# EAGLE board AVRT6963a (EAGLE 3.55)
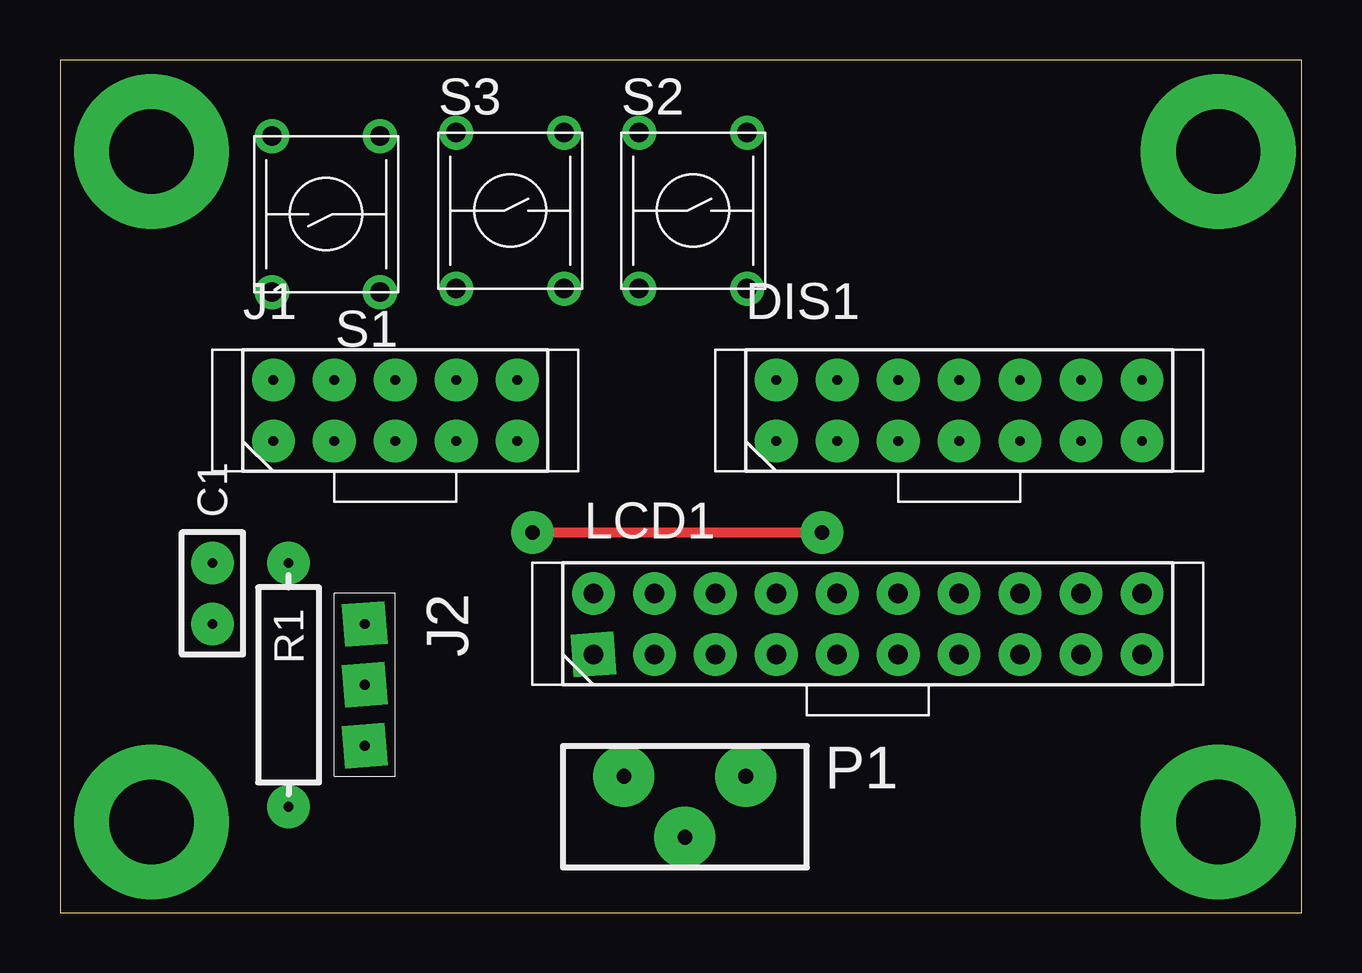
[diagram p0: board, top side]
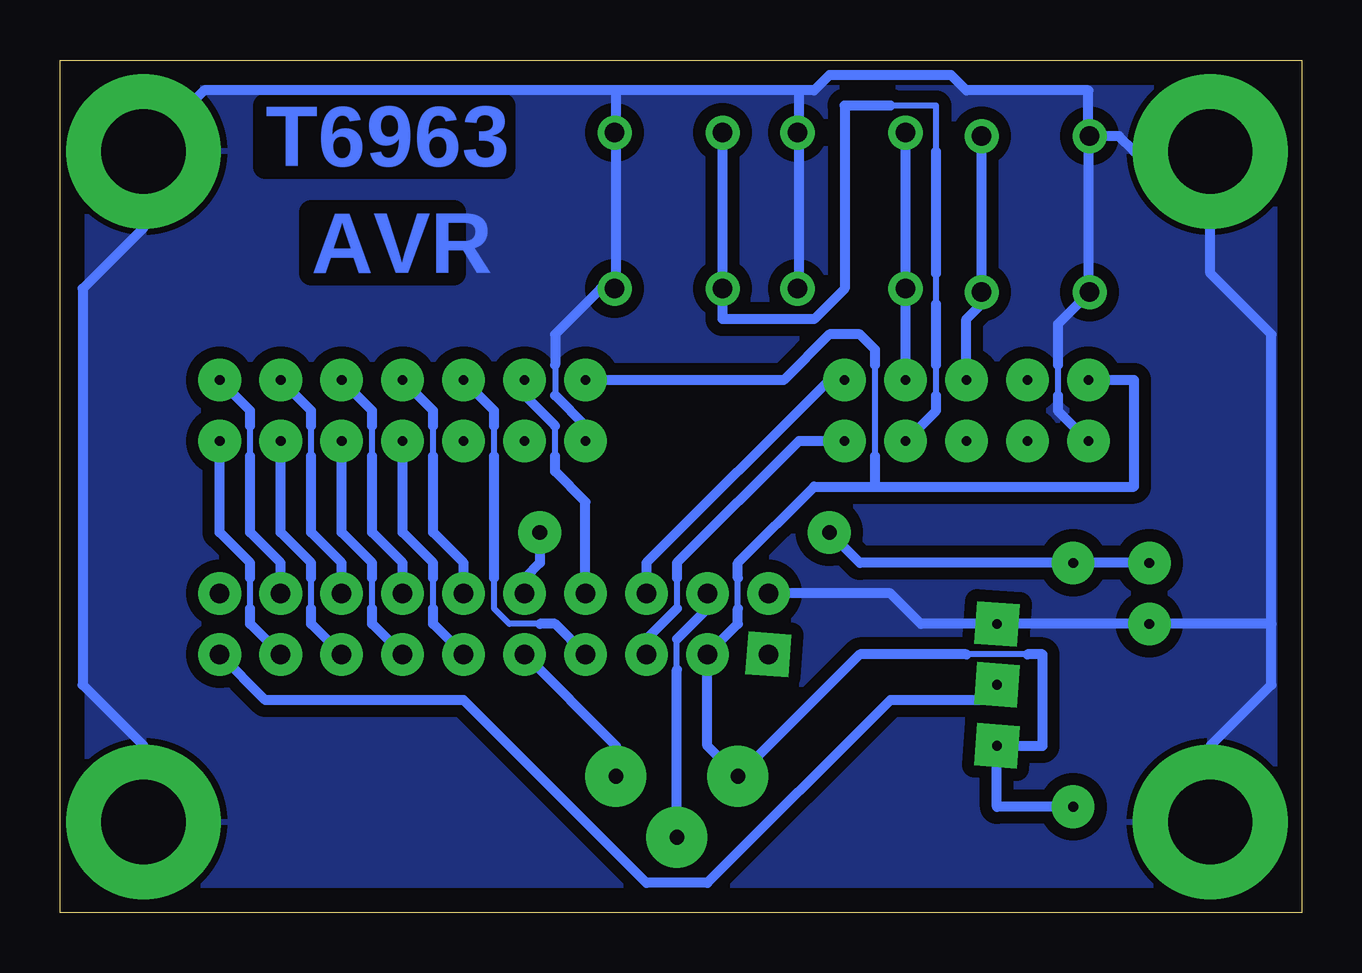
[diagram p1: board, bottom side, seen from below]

Size 51.74 x 35.54 mm. Coordinates in mm from the lower left corner, seen from the top.
Outline: 0,35.54 0,0 51.74,0 51.74,35.54 0,35.54
Copper layers used: Top, Bottom

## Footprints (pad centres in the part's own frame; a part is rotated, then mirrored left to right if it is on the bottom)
RM2,5 = drill 0.406 pad 1.778 round:  -1.27,0;  1.27,0
7 = drill 0.406 pad 1.778 round:  0,0;  2.54,0;  5.08,0;  7.62,0;  10.16,0;  10.16,2.54;  7.62,2.54;  5.08,2.54;  2.54,2.54;  0,2.54;  12.7,0;  12.7,2.54;  15.24,0;  15.24,2.54
5 = drill 0.406 pad 1.778 round:  0,0;  2.54,0;  5.08,0;  7.62,0;  10.16,0;  10.16,2.54;  7.62,2.54;  5.08,2.54;  2.54,2.54;  0,2.54
MPER_3 = drill 0.406 pad 1.778 square:  -2.54,0;  0,0;  2.54,0
10 = drill 0.813 pad 1.778 square:  0,0 | drill 0.813 pad 1.778 round:  2.54,0;  5.08,0;  7.62,0;  10.16,0;  12.7,0;  15.24,0;  15.24,2.54;  12.7,2.54;  10.16,2.54;  7.62,2.54;  5.08,2.54;  2.54,2.54;  0,2.54;  17.78,0;  17.78,2.54;  20.32,0;  20.32,2.54;  22.86,0;  22.86,2.54
IM_STE = drill 0.61 pad 2.54 round:  -2.54,-1.27;  2.54,-1.27;  0,1.27
S04 = drill 0.406 pad 1.778 round:  -5.08,0;  5.08,0
US = drill 0.813 pad 1.422 round:  0,0;  4.5,0;  4.5,6.5;  0,6.5
HRUNG = drill 3.505 pad 6.452 round:  0,0

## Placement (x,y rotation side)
C1  C100NK  [RM2,5]  6.35,13.32 90 top
DIS1  LCD  [7]  29.84,19.66 0 top
J1  8BITPORT  [5]  8.89,19.66 0 top
J2  JUMPER_3  [MPER_3]  12.7,9.51 270 top
LCD1  WG24064A  [10]  22.23,10.78 0 top
P1  47k  [IM_STE]  26.04,4.43 180 top
R1  10k  [S04]  9.53,9.51 270 top
S1  [US]  13.34,32.36 180 top
S2  [US]  24.13,26.02 0 top
S3  [US]  16.51,26.02 0 top
U$4  BOHRUNG  [HRUNG]  48.26,3.79 270 top
U$9  BOHRUNG  [HRUNG]  3.81,3.79 270 top
U$16  BOHRUNG  [HRUNG]  3.81,31.73 0 top
U$17  BOHRUNG  [HRUNG]  48.26,31.73 0 top

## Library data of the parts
C1 DIS1 J1 J2 LCD1 P1 R1 = holg_plt
S1-S3 = taster1
U$4 U$9 U$16 U$17 = holgnorm

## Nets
+5V: DIS1. J1. J2. LCD1. P1. R1.
/CE: DIS1. LCD1.
/RD: J1. LCD1.
/WR: J1. LCD1.
A0: DIS1. LCD1.
D0: DIS1. LCD1.
D1: DIS1. LCD1.
D2: DIS1. LCD1.
D3: DIS1. LCD1.
D4: DIS1. LCD1.
D5: DIS1. LCD1.
D6: DIS1. LCD1.
D7: DIS1. LCD1.
GND: C1. DIS1. J1. J2. LCD1. S1. S2. S3. U$4. U$9. U$16. U$17.
N$1: J1. S3.
N$2: C1. LCD1. R1.
N$3: J2. LCD1.
N$4: LCD1. P1.
N$5: LCD1. P1.
N$6: J1. S2.
N$7: J1. S1.

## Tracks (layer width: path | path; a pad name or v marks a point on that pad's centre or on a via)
+5V
  Bottom 0.254: 17.78,19.03 17.78,22.84 | 23.5,12.68 23.5,13.95 | 11.43,10.78 13.97,10.78
  Bottom 0.406: J1. 6.99,22.21 6.99,17.76 17.78,17.76 | R1. 12.7,4.43 J2. 10.79,6.97 10.79,10.78 11.43,10.78 | 29.84,22.21 21.59,22.21 19.68,24.11 18.41,24.11 17.78,23.48 17.78,22.84 | 17.78,17.76 17.78,19.03 | 23.5,12.68 23.5,12.04 24.77,10.78 24.77,6.97 23.5,5.7 18.41,10.78 13.97,10.78 | 23.5,13.95 23.5,14.59 20.32,17.76 17.78,17.76
/CE
  Bottom 0.254: 33.66,19.03 33.66,20.3 | 31.75,12.04 33.02,12.04 33.66,12.68 33.66,13.95
  Bottom 0.406: 29.84,10.78 31.11,12.04 31.75,12.04 | 34.92,22.21 33.66,20.93 33.66,20.3 | 33.66,13.95 33.66,19.03
/RD
  Bottom 0.406: 19.05,22.21 19.68,22.21 27.3,14.59 27.3,13.32
/WR
  Bottom 0.254: 26.04,13.95 26.04,12.68
  Bottom 0.406: 19.05,19.66 20.95,19.66 26.04,14.59 26.04,13.95 | 27.3,10.78 27.3,11.41 26.04,12.68
A0
  Bottom 0.254: 31.11,19.03 31.11,20.3
  Bottom 0.406: 32.38,22.21 32.38,21.57 31.11,20.3 | 29.84,13.32 29.84,17.12 31.11,18.39 31.11,19.03
D0
  Bottom 0.254: 36.2,12.68 36.2,13.95
  Bottom 0.406: 34.92,10.78 36.2,12.04 36.2,12.68 | 37.47,19.66 37.47,15.86 36.2,14.59 36.2,13.95
D1
  Bottom 0.254: 36.2,19.03 36.2,20.3
  Bottom 0.406: 37.47,22.21 36.2,20.93 36.2,20.3 | 34.92,13.32 34.92,14.59 36.2,15.86 36.2,19.03
D2
  Bottom 0.254: 38.73,12.68 38.73,13.95
  Bottom 0.406: 37.47,10.78 38.73,12.04 38.73,12.68 | 40.01,19.66 40.01,15.86 38.73,14.59 38.73,13.95
D3
  Bottom 0.254: 38.73,19.03 38.73,20.3
  Bottom 0.406: 40.01,22.21 38.73,20.93 38.73,20.3 | 37.47,13.32 37.47,14.59 38.73,15.86 38.73,19.03
D4
  Bottom 0.254: 41.27,12.68 41.27,13.95
  Bottom 0.406: 40.01,10.78 41.27,12.04 41.27,12.68 | 42.55,19.66 42.55,15.86 41.27,14.59 41.27,13.95
D5
  Bottom 0.254: 41.27,19.03 41.27,20.3
  Bottom 0.406: 42.55,22.21 41.27,20.93 41.27,20.3 | 40.01,13.32 40.01,14.59 41.27,15.86 41.27,19.03
D6
  Bottom 0.254: 43.81,12.68 43.81,13.95
  Bottom 0.406: 45.09,19.66 45.09,15.86 43.81,14.59 43.81,13.95 | 42.55,10.78 43.81,12.04 43.81,12.68
D7
  Bottom 0.254: 43.81,19.03 43.81,20.3
  Bottom 0.406: DIS1. 43.81,20.93 43.81,20.3 | 42.55,13.32 42.55,14.59 43.81,15.86 43.81,19.03
GND
  Bottom 0.254: 31.11,22.84 31.11,21.57 | 10.16,22.84 10.16,21.57
  Bottom 0.406: 29.84,19.66 29.84,20.3 31.11,21.57 | 31.11,22.84 31.11,24.11 29.21,26.02 28.63,26.02 28.57,26.07 28.57,32.46 28.63,32.51 28.57,32.57 28.57,34.27 | 8.89,19.66 10.16,20.93 10.16,21.57 | 10.16,22.84 10.16,24.54 8.84,25.87 8.89,25.92 8.89,32.31 8.84,32.36 | 21.01,26.02 20.95,26.07 20.95,32.46 21.01,32.51 20.95,32.57 20.95,34.27 | 20.95,34.27 28.57,34.27 | 8.84,32.36 8.89,32.42 8.89,34.27 13.97,34.27 14.61,34.9 19.68,34.9 20.32,34.27 20.95,34.27 | 8.84,32.36 7.62,32.36 6.99,31.73 U$16. 3.81,26.65 1.27,24.11 1.27,12.04 | 28.57,34.27 45.72,34.27 U$17. 48.26,28.55 50.8,26.02 50.8,9.51 48.26,6.97 U$4. | U$9. 3.81,6.97 1.27,9.51 1.27,12.04 | 22.23,13.32 17.14,13.32 15.88,12.04 12.7,12.04 6.35,12.04 1.27,12.04
  pour Bottom (isolate 0.508): 0.64,34.9 0.64,0.61 50.8,0.61 50.8,34.9
N$1
  Bottom 0.406: 16.51,22.21 16.51,26.02 S3.
N$2  (via drill 0.61 pad 1.78)
  Top 0.406: v19.68,15.86 v31.75,15.86
  Bottom 0.406: C1. 9.53,14.59 18.41,14.59 v19.68,15.86 | 32.38,13.32 32.38,13.95 31.75,14.59 v31.75,15.86
N$3
  Bottom 0.406: 12.7,9.51 13.34,8.87 17.14,8.87 24.77,1.25 27.3,1.25 34.92,8.87 43.18,8.87 45.09,10.78
N$4
  Bottom 0.254: 26.04,10.14 26.04,11.41
  Bottom 0.406: 24.77,13.32 24.77,12.68 26.04,11.41 | P1. 26.04,10.14
N$5
  Bottom 0.406: 32.38,10.78 28.57,6.97 28.57,5.7
N$6
  Bottom 0.254: 15.24,21.57 15.24,22.84 | 15.24,25.38 15.24,26.65 | 17.14,33.63 15.24,33.63 15.24,31.73
  Bottom 0.406: 16.51,19.66 15.24,20.93 15.24,21.57 | S2. 24.13,26.02 24.13,24.75 20.32,24.75 19.05,26.02 19.05,33.63 17.14,33.63 | 15.24,22.84 15.24,25.38 | 15.24,26.65 15.24,31.73
N$7
  Bottom 0.406: 13.97,22.21 13.97,24.75 13.34,25.38 S1. 13.34,32.36

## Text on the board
Bottom: T6963 | AVR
